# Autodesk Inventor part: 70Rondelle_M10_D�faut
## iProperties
Created: 2011-01
Part Number: 70Rondelle_M10_D�faut
Document SubType Name: Modeling
Designer: eric
Density: 1 g/cm^3
Mass: 0.587085 g
Surface Area: 7.91289 cm^2
Volume: 0.587085 cm^3
Author: eric
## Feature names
1. Base1
